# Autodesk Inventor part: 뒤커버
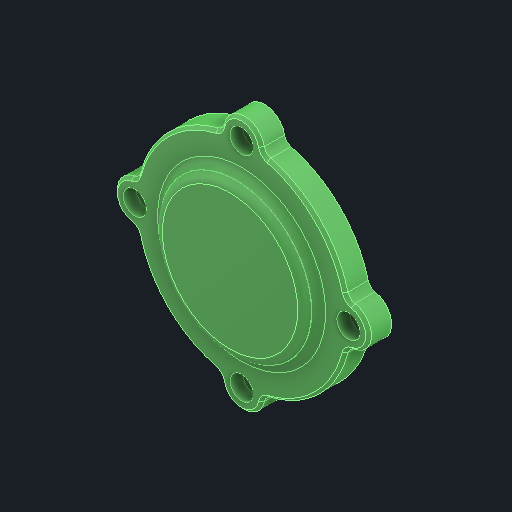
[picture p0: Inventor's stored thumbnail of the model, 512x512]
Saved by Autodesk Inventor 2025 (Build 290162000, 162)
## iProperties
Created: 2025-08
Part Number: 뒤커버
Material: 알루미늄 6061
Document SubType Name: Modeling
Designer: infra012
Density: 2.71 g/cm^3
Appearance: 기본값
Company: 한국ATC센터
Author: jhkim
Sending System: Autodesk Inventor 2026
Preprocessor: ST-DEVELOPER v20.1
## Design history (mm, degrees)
sketch "스케치1"
  geometry: 1 further point
  constraints: 1 other
feature "솔리드1"
node "솔리드2"
